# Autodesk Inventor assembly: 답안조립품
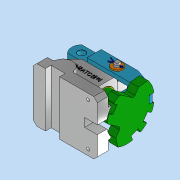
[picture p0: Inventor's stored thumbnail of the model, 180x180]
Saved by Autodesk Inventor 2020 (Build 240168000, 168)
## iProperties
Created: 2022-08
Part Number: 답안조립품
Document SubType Name: Assembly
Designer: user
Author: user
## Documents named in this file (8)
- C:\Users\user\Desktop\720806V1012\답안조립품.iam
- C:\Users\user\Desktop\720806V1012\본체.ipt
- C:\Users\user\Desktop\720806V1012\부시.ipt
- C:\Users\user\Desktop\720806V1012\분할대.ipt
- C:\Users\user\Desktop\720806V1012\분할축.ipt
- C:\Users\user\Desktop\720806V1012\분할핀.ipt
- C:\Users\user\Desktop\720806V1012\와셔.ipt
- C:\Users\user\Desktop\720806V1012\클레비스핀.ipt
